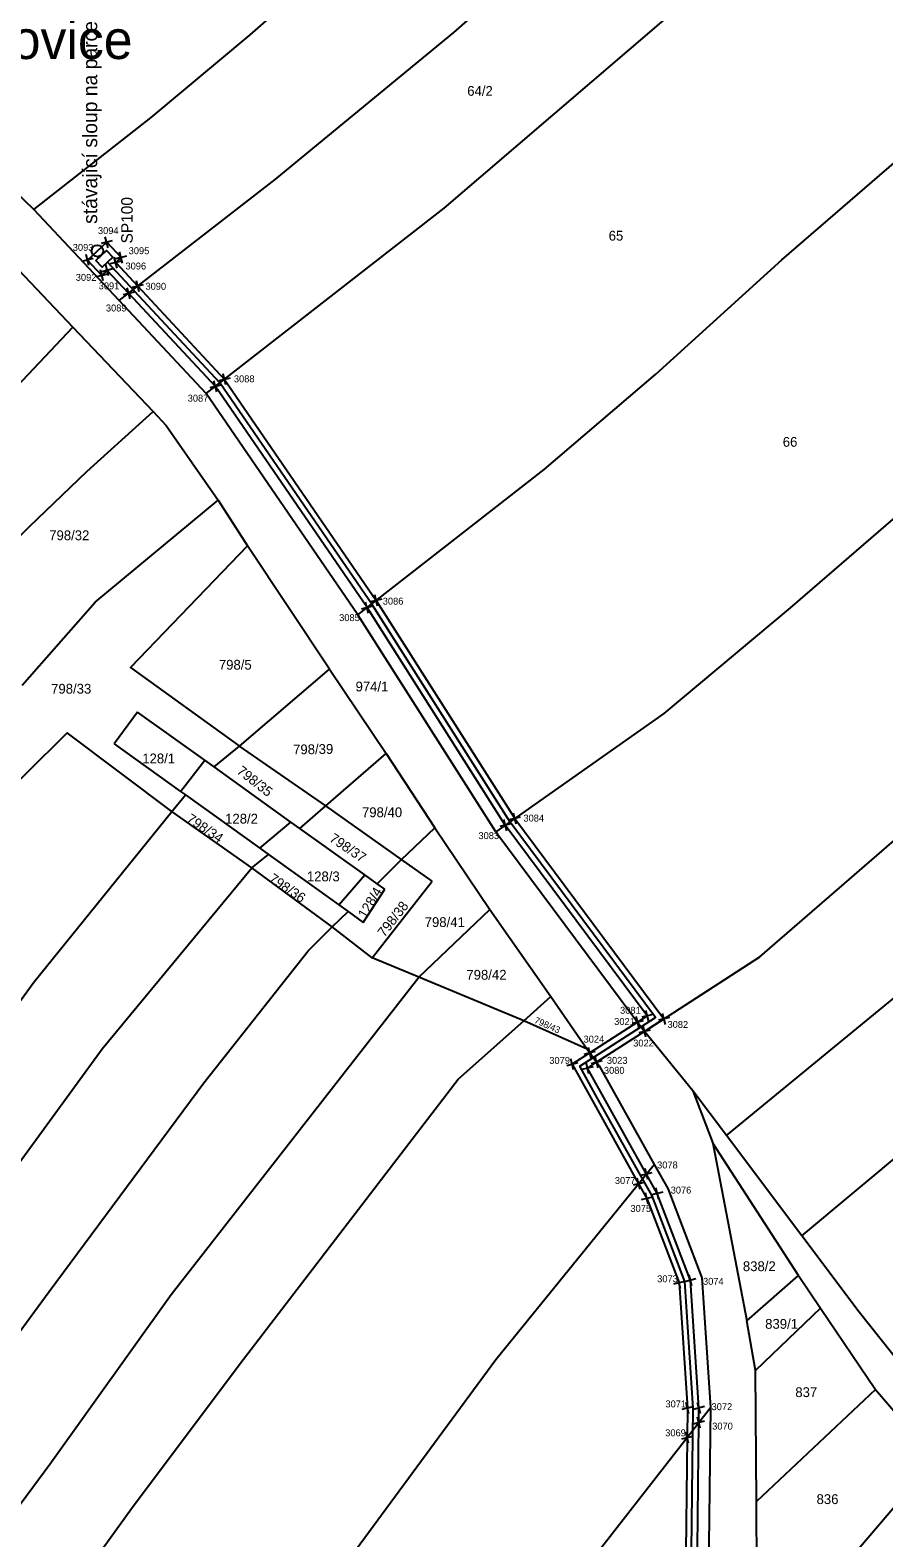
# Model space of a CAD drawing. Extents: x -7476540 to -746055, y -11317203 to -1129777.
# Drawn here: x -747694.4 to -747546.5, y -1131418.4 to -1131157.3 of the extents above; entities that cross this region are included whole.
import ezdxf

# ---------------------------------------------------------------- set-up
doc = ezdxf.new("R2010")
doc.units = 0
for name, color, linetype in [('_TRASA_vedení kabelu_CEZ', 7, 'Continuous'), ('Hranice parcel', 7, 'Continuous'), ('obvod_stavby_DZ_DO_ostatní', 7, 'Continuous'), ('obvod_stavby_DZ_DO_ZPF', 7, 'Continuous'), ('Parcelní čísla', 7, 'Continuous'), ('Pop  PČ popisy', 7, 'Continuous'), ('Vrstva 60', 7, 'Continuous')]:
    doc.layers.add(name, color=color, linetype=linetype)

# ---------------------------------------------------------------- blocks, each defined once
blk = doc.blocks.new('POINT_DISPLAY')
for p, q in [((-0.7, -0.7), (0.7, 0.7)), ((-0.7, 0.7), (0.7, -0.7))]:
    blk.add_line(p, q)

msp = doc.modelspace()

# ---------------------------------------------------------------- linework, layer by layer
msp.add_circle((-747682.72, -1131195.55), 1)
msp.add_circle((-747682.72, -1131195.55), 1)
msp.add_circle((-747682.72, -1131195.55), 1)
at = {"layer": '_TRASA_vedení kabelu_CEZ'}
msp.add_lwpolyline([(-747683.01, -1131197.18), (-747681.15, -1131195.45), (-747680.03, -1131196.64), (-747681.89, -1131198.38)], close=True, dxfattribs=at)
msp.add_lwpolyline([(-747579.88, -1131425.59), (-747579.54, -1131395.96), (-747581.01, -1131374.06), (-747586.67, -1131359.23), (-747588.9, -1131355.23), (-747596.45, -1131341.71), (-747599.17, -1131336.75), (-747586.05, -1131328.3), (-747611.25, -1131294.46), (-747635.1, -1131256.91), (-747661.52, -1131218.38), (-747680.96, -1131197.51)], dxfattribs=at)
at = {"layer": 'Hranice parcel'}
for p, q in [((-747693.71, -1131188.35), (-747705.95, -1131176.64)), ((-747678.94, -1131204.15), (-747693.71, -1131188.35)), ((-747699.59, -1131195.48), (-747686.96, -1131208.76)), ((-747663.87, -1131220.26), (-747678.94, -1131204.15)), ((-747686.96, -1131208.76), (-747673.07, -1131223.37)), ((-747637.6, -1131258.56), (-747663.87, -1131220.26)), ((-747661.79, -1131238.73), (-747656.71, -1131246.65)), ((-747642.55, -1131267.96), (-747656.71, -1131246.65)), ((-747613.72, -1131296.16), (-747637.6, -1131258.56)), ((-747658.09, -1131281.3), (-747642.55, -1131267.96)), ((-747642.55, -1131267.96), (-747632.73, -1131282.6)), ((-747675.77, -1131275.42), (-747679.79, -1131280.94)), ((-747664.12, -1131283.77), (-747675.77, -1131275.42)), ((-747679.79, -1131280.94), (-747668.32, -1131289.17)), ((-747662.52, -1131284.92), (-747658.09, -1131281.3)), ((-747643.16, -1131291.66), (-747658.09, -1131281.3)), ((-747668.32, -1131289.17), (-747664.12, -1131283.77)), ((-747662.52, -1131284.92), (-747664.12, -1131283.77)), ((-747643.16, -1131291.66), (-747632.73, -1131282.6)), ((-747632.73, -1131282.6), (-747624.26, -1131295.45)), ((-747649.2, -1131294.46), (-747662.52, -1131284.92)), ((-747669.82, -1131292.66), (-747667.48, -1131289.77)), ((-747668.32, -1131289.17), (-747667.48, -1131289.77)), ((-747667.48, -1131289.77), (-747654.61, -1131299)), ((-747647.65, -1131295.57), (-747643.16, -1131291.66)), ((-747630.05, -1131300.93), (-747643.16, -1131291.66)), ((-747656, -1131302.39), (-747669.82, -1131292.66)), ((-747654.61, -1131299), (-747649.2, -1131294.46)), ((-747647.65, -1131295.57), (-747649.2, -1131294.46)), ((-747636.4, -1131303.63), (-747647.65, -1131295.57)), ((-747630.05, -1131300.93), (-747624.26, -1131295.45)), ((-747624.26, -1131295.45), (-747614.76, -1131309.6)), ((-747613.72, -1131296.16), (-747587.97, -1131330.74)), ((-747656, -1131302.39), (-747653.1, -1131300.08)), ((-747654.61, -1131299), (-747653.1, -1131300.08)), ((-747653.1, -1131300.08), (-747640.91, -1131308.82)), ((-747642.09, -1131312.59), (-747656, -1131302.39)), ((-747634.28, -1131305.15), (-747630.05, -1131300.93)), ((-747624.72, -1131304.69), (-747630.05, -1131300.93)), ((-747640.91, -1131308.82), (-747636.4, -1131303.63)), ((-747634.28, -1131305.15), (-747636.4, -1131303.63)), ((-747635.14, -1131317.96), (-747624.72, -1131304.69)), ((-747632.97, -1131306.09), (-747634.28, -1131305.15)), ((-747636.7, -1131311.84), (-747632.97, -1131306.09)), ((-747642.09, -1131312.59), (-747639.3, -1131309.98)), ((-747640.91, -1131308.82), (-747639.3, -1131309.98)), ((-747639.3, -1131309.98), (-747636.7, -1131311.84)), ((-747627.04, -1131321.32), (-747614.76, -1131309.6)), ((-747614.76, -1131309.6), (-747604.21, -1131324.68)), ((-747635.14, -1131317.96), (-747642.09, -1131312.59)), ((-747627.04, -1131321.32), (-747635.14, -1131317.96)), ((-747608.88, -1131328.87), (-747627.04, -1131321.32)), ((-747608.88, -1131328.87), (-747604.21, -1131324.68)), ((-747604.21, -1131324.68), (-747597.93, -1131333.8)), ((-747597.93, -1131333.8), (-747608.88, -1131328.87)), ((-747579.59, -1131341), (-747587.97, -1131330.74)), ((-747573.75, -1131348.78), (-747579.59, -1131341)), ((-747579.59, -1131341), (-747576.14, -1131350.08)), ((-747560.74, -1131366.12), (-747573.75, -1131348.78)), ((-747576.14, -1131350.08), (-747570.26, -1131380.88)), ((-747561.31, -1131373.03), (-747576.14, -1131350.08)), ((-747570.26, -1131380.88), (-747561.31, -1131373.03)), ((-747561.31, -1131373.03), (-747557.5, -1131378.68)), ((-747568.77, -1131389.44), (-747570.26, -1131380.88)), ((-747557.5, -1131378.68), (-747568.77, -1131389.44)), ((-747557.5, -1131378.68), (-747547.95, -1131392.74)), ((-747568.57, -1131412.15), (-747568.77, -1131389.44)), ((-747547.95, -1131392.74), (-747568.57, -1131412.15)), ((-747547.95, -1131392.74), (-747537.66, -1131404.8)), ((-747576.54, -1131395.88), (-747576.88, -1131425.52)), ((-747537.66, -1131404.8), (-747568.52, -1131441.05)), ((-747568.52, -1131441.05), (-747568.57, -1131412.15))]:
    msp.add_line(p, q, dxfattribs=at)
for points in [[(-747693.71, -1131188.35), (-747673.39, -1131172.41), (-747656.27, -1131158.12), (-747617.7, -1131124.35), (-747583.1, -1131094.79)], [(-747678.94, -1131204.15), (-747651.91, -1131183.16), (-747620.97, -1131157.74), (-747567.13, -1131110.4)], [(-747663.87, -1131220.26), (-747622.68, -1131188.16), (-747577.82, -1131149.69), (-747551.23, -1131125.94)], [(-747637.6, -1131258.56), (-747605.36, -1131233.4), (-747586.04, -1131216.89), (-747564.17, -1131197.09), (-747518.15, -1131157.34)], [(-747478.68, -1131189), (-747516.61, -1131217.55), (-747562.75, -1131257.36), (-747584.62, -1131275.69), (-747613.72, -1131296.16)], [(-747719.59, -1131243.31), (-747710.17, -1131233.27), (-747686.96, -1131208.76)], [(-747587.97, -1131330.74), (-747567.99, -1131317.8), (-747522.26, -1131278.21), (-747503.48, -1131261.46), (-747452.5, -1131218.84)], [(-747705.1, -1131253.98), (-747694.48, -1131243.3), (-747684.57, -1131233.76), (-747673.07, -1131223.37)], [(-747673.07, -1131223.37), (-747670.79, -1131225.76), (-747661.79, -1131238.73)], [(-747695.74, -1131270.78), (-747683.08, -1131256.39), (-747661.79, -1131238.73)], [(-747573.75, -1131348.78), (-747519.29, -1131304), (-747475.75, -1131265.13), (-747451.48, -1131246.17), (-747439.12, -1131238.12)], [(-747656.71, -1131246.65), (-747676.97, -1131267.67), (-747658.09, -1131281.3)], [(-747560.74, -1131366.12), (-747532.83, -1131342.86), (-747438.82, -1131264.87), (-747425.11, -1131256.95)], [(-747669.82, -1131292.66), (-747687.96, -1131278.99), (-747702.43, -1131293.35), (-747710.63, -1131287.46)], [(-747915.42, -1131619.45), (-747873.23, -1131566.86), (-747843.82, -1131525.97), (-747806.53, -1131475.44), (-747778.43, -1131437.61), (-747729.49, -1131371.5), (-747693.71, -1131322.2), (-747669.82, -1131292.66)], [(-747895.76, -1131621.42), (-747861.58, -1131578.6), (-747835.67, -1131543.4), (-747806.42, -1131503.18), (-747795.07, -1131488.14), (-747755.24, -1131433.32), (-747715.49, -1131379.82), (-747681.87, -1131333.76), (-747656, -1131302.39)], [(-747879, -1131625.66), (-747851.66, -1131591.69), (-747829.65, -1131563.42), (-747808.64, -1131535.34), (-747757.65, -1131465.52), (-747713.97, -1131406.96), (-747691.09, -1131375.78), (-747664.28, -1131339.63), (-747646.2, -1131316.75), (-747642.09, -1131312.59)], [(-747860.06, -1131629.88), (-747832.75, -1131596.26), (-747816.97, -1131575.83), (-747776.82, -1131523.47), (-747762.78, -1131503.59), (-747734.31, -1131465.05), (-747710.2, -1131431.58), (-747690.98, -1131405.7), (-747669.96, -1131376.28), (-747627.04, -1131321.32)], [(-747842.01, -1131634.16), (-747811.79, -1131593.14), (-747801.87, -1131584.09), (-747752.07, -1131516.87), (-747707.12, -1131455.02), (-747691.23, -1131433.37), (-747676.82, -1131413.33), (-747658, -1131388.25), (-747620.26, -1131339), (-747608.88, -1131328.87)], [(-747597.93, -1131333.8), (-747595.82, -1131336.69), (-747586.28, -1131353.77)], [(-747806.67, -1131645.86), (-747760.08, -1131583.56), (-747741.05, -1131557.9), (-747711.67, -1131520.04), (-747658.45, -1131448.35), (-747613.7, -1131387.55), (-747586.28, -1131353.77)], [(-747586.28, -1131353.77), (-747583.94, -1131357.96), (-747578.05, -1131373.41), (-747576.54, -1131395.88)], [(-747534.26, -1131400.17), (-747550.8, -1131379.36), (-747560.74, -1131366.12)], [(-747772.35, -1131654.05), (-747742.69, -1131616.2), (-747708.15, -1131571.7), (-747696.05, -1131555.49), (-747654.43, -1131499.96), (-747614.66, -1131444.39), (-747602.9, -1131429.72), (-747576.54, -1131395.88)]]:
    msp.add_lwpolyline(points, dxfattribs=at)
at = {"layer": 'obvod_stavby_DZ_DO_ostatní'}
for p, q in [((-747589.17, -1131329.12), (-747597.45, -1131334.46)), ((-747587.97, -1131330.74), (-747596.27, -1131336.08))]:
    msp.add_line(p, q, dxfattribs=at)
at = {"layer": 'obvod_stavby_DZ_DO_ZPF'}
for points in [[(-747589.17, -1131329.12), (-747587.49, -1131328.04), (-747612.08, -1131295.01), (-747636.02, -1131257.33), (-747662.29, -1131219.03), (-747677.3, -1131202.91), (-747681.01, -1131198.93), (-747681.94, -1131199.79), (-747684.42, -1131197.13), (-747681.1, -1131194.04), (-747678.62, -1131196.7), (-747679.55, -1131197.56), (-747675.73, -1131201.66), (-747660.68, -1131217.83), (-747634.44, -1131256.09), (-747610.45, -1131293.86), (-747584.6, -1131328.56), (-747587.97, -1131330.74)], [(-747578.88, -1131425.6), (-747578.57, -1131398.49), (-747578.54, -1131395.94), (-747580.03, -1131373.84), (-747585.76, -1131358.8), (-747587.64, -1131355.44), (-747597.84, -1131337.09), (-747596.27, -1131336.08), (-747597.45, -1131334.46), (-747600.49, -1131336.42), (-747588.99, -1131357.11), (-747587.57, -1131359.66), (-747582, -1131374.28), (-747580.54, -1131395.98), (-747580.6, -1131401.09), (-747580.88, -1131425.73)]]:
    msp.add_lwpolyline(points, dxfattribs=at)
at = {"layer": 'Vrstva 60'}
for p, q in [((-747681.1, -1131194.04), (-747681.1, -1131194.04)), ((-747684.42, -1131197.13), (-747684.42, -1131197.13)), ((-747679.55, -1131197.56), (-747679.55, -1131197.56)), ((-747678.62, -1131196.7), (-747678.62, -1131196.7)), ((-747681.94, -1131199.79), (-747681.94, -1131199.79)), ((-747681.01, -1131198.93), (-747681.01, -1131198.93)), ((-747677.3, -1131202.91), (-747677.3, -1131202.91)), ((-747675.73, -1131201.66), (-747675.73, -1131201.66)), ((-747662.29, -1131219.03), (-747662.29, -1131219.03)), ((-747660.71, -1131217.8), (-747660.71, -1131217.8)), ((-747636.02, -1131257.33), (-747636.02, -1131257.33)), ((-747634.44, -1131256.09), (-747634.44, -1131256.09)), ((-747610.45, -1131293.86), (-747610.45, -1131293.86)), ((-747612.08, -1131295.01), (-747612.08, -1131295.01)), ((-747587.49, -1131328.04), (-747587.49, -1131328.04)), ((-747584.6, -1131328.56), (-747584.6, -1131328.56)), ((-747589.17, -1131329.12), (-747589.17, -1131329.12)), ((-747587.97, -1131330.74), (-747587.97, -1131330.74)), ((-747600.49, -1131336.42), (-747600.49, -1131336.42)), ((-747597.45, -1131334.46), (-747597.45, -1131334.46)), ((-747596.27, -1131336.08), (-747596.27, -1131336.08)), ((-747597.84, -1131337.09), (-747597.84, -1131337.09)), ((-747588.99, -1131357.11), (-747588.99, -1131357.11)), ((-747587.64, -1131355.44), (-747587.64, -1131355.44)), ((-747587.57, -1131359.66), (-747587.57, -1131359.66)), ((-747585.76, -1131358.8), (-747585.76, -1131358.8)), ((-747582, -1131374.28), (-747582, -1131374.28)), ((-747580.03, -1131373.84), (-747580.03, -1131373.84)), ((-747580.54, -1131395.98), (-747580.54, -1131395.98)), ((-747578.54, -1131395.94), (-747578.54, -1131395.94)), ((-747578.57, -1131398.49), (-747578.57, -1131398.49)), ((-747580.6, -1131401.09), (-747580.6, -1131401.09))]:
    msp.add_line(p, q, dxfattribs=at)

# ---------------------------------------------------------------- block references
at = {"layer": 'obvod_stavby_DZ_DO_ostatní', "rotation": 149.23018890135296}
for p in [(-747589.17, -1131329.12), (-747587.97, -1131330.74), (-747597.45, -1131334.46), (-747596.27, -1131336.08)]:
    msp.add_blockref('POINT_DISPLAY', p, dxfattribs=at)
at = {"layer": 'obvod_stavby_DZ_DO_ZPF', "rotation": 149.23018890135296}
for p in [(-747681.1, -1131194.04), (-747678.62, -1131196.69), (-747684.42, -1131197.13), (-747681.01, -1131198.92), (-747679.55, -1131197.56), (-747681.94, -1131199.79), (-747675.73, -1131201.66), (-747677.3, -1131202.91), (-747662.29, -1131219.02), (-747660.71, -1131217.8), (-747634.44, -1131256.09), (-747636.02, -1131257.33), (-747612.08, -1131295.01), (-747610.44, -1131293.86), (-747587.49, -1131328.04), (-747584.6, -1131328.56), (-747600.49, -1131336.42), (-747597.84, -1131337.09), (-747587.64, -1131355.44), (-747588.99, -1131357.11), (-747587.57, -1131359.66), (-747585.76, -1131358.8), (-747582, -1131374.27), (-747580.02, -1131373.84), (-747580.54, -1131395.98), (-747578.54, -1131395.94), (-747578.57, -1131398.49), (-747580.6, -1131401.11)]:
    msp.add_blockref('POINT_DISPLAY', p, dxfattribs=at)

# ---------------------------------------------------------------- texts
at = {"layer": '_TRASA_vedení kabelu_CEZ'}
for s, height, p in [('stávající sloup na parcele 64/1', 2.5, (-747682.75, -1131190.86)), ('SP100', 2, (-747676.6, -1131194.25))]:
    msp.add_text(s, height=height, rotation=90, dxfattribs=at).set_placement(p)
at = {"layer": 'Parcelní čísla'}
for s, p in [('64/2', (-747618.67, -1131168.68)), ('65', (-747594.18, -1131193.76)), ('66', (-747564.03, -1131229.47)), ('798/32', (-747691.06, -1131245.65)), ('798/5', (-747661.68, -1131268.07)), ('798/33', (-747690.73, -1131272.23)), ('974/1', (-747638.01, -1131271.84)), ('128/1', (-747674.95, -1131284.3)), ('798/40', (-747636.9, -1131293.62)), ('128/2', (-747660.6, -1131294.73)), ('128/3', (-747646.44, -1131304.73)), ('798/41', (-747626.04, -1131312.65)), ('798/42', (-747618.82, -1131321.77)), ('838/2', (-747570.94, -1131372.25)), ('839/1', (-747567.08, -1131382.23)), ('837', (-747561.86, -1131394.06)), ('836', (-747558.18, -1131412.59))]:
    msp.add_text(s, height=1.7, dxfattribs=at).set_placement(p)
for s, height, rotation, p in [('798/39', 1.7, 1, (-747648.81, -1131282.76)), ('798/35', 1.7, 322, (-747658.7, -1131285.91)), ('798/34', 1.7, 326, (-747667.43, -1131294.3)), ('798/37', 1.7, 326, (-747642.68, -1131297.68)), ('798/36', 1.7, 326, (-747653.17, -1131304.65)), ('128/4', 1.7, 59, (-747636.25, -1131311.3)), ('798/38', 1.7, 52, (-747633.01, -1131314.51)), ('798/43', 1.14, 336, (-747607.16, -1131329.21))]:
    msp.add_text(s, height=height, rotation=rotation, dxfattribs=at).set_placement(p)
at = {"layer": 'Pop  PČ popisy'}
msp.add_text('Bežerovice', height=6.7, dxfattribs=at).set_placement((-747720.95, -1131162.31))
at = {"layer": 'Vrstva 60'}
for s, p in [('3094', (-747682.62, -1131192.63)), ('3093', (-747686.98, -1131195.54)), ('3095', (-747677.3, -1131196.11)), ('3096', (-747677.85, -1131198.76)), ('3092', (-747686.46, -1131200.73)), ('3091', (-747682.49, -1131202.2)), ('3090', (-747674.39, -1131202.27)), ('3089', (-747681.24, -1131206.03)), ('3088', (-747659.08, -1131218.3)), ('3087', (-747667.08, -1131221.65)), ('3086', (-747633.3, -1131256.8)), ('3085', (-747640.85, -1131259.66)), ('3084', (-747608.94, -1131294.38)), ('3083', (-747616.73, -1131297.42)), ('3021', (-747593.23, -1131329.61)), ('3081', (-747592.21, -1131327.67)), ('3082', (-747583.99, -1131330.12)), ('3024', (-747598.53, -1131332.67)), ('3022', (-747589.93, -1131333.34)), ('3079', (-747604.46, -1131336.35)), ('3023', (-747594.49, -1131336.34)), ('3080', (-747595, -1131338.07)), ('3078', (-747585.79, -1131354.46)), ('3077', (-747593.11, -1131357.16)), ('3076', (-747583.44, -1131358.81)), ('3075', (-747590.41, -1131361.99)), ('3073', (-747585.78, -1131374.17)), ('3074', (-747577.84, -1131374.61)), ('3071', (-747584.35, -1131395.84)), ('3072', (-747576.36, -1131396.32)), ('3070', (-747576.25, -1131399.69)), ('3069', (-747584.39, -1131400.85))]:
    msp.add_text(s, height=1.2, dxfattribs=at).set_placement(p)

doc.saveas('drawing.dxf')
